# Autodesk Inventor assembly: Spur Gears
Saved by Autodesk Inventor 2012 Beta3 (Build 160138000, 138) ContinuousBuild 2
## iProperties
Created: 2010-12
Part Number: Spur Gears
Document SubType Name: Assembly
Designer: Thom Tremblay
Categories: <?xml version="1.0" encoding="UTF-16"?> <MemberInstance><Categories><FamilyTemplate/><ParamToTemplateMap><ParamToTemplate><ParamToTemplate CategoryParameter="//
ClientObjectVersion: 1
Author: Thom Tremblay
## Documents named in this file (1)
- C:\Inventor 2012 Essentials\Assemblies\Chapter 6\c6-01\Design Accelerator\Spur Gears1.iam
